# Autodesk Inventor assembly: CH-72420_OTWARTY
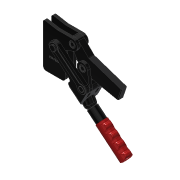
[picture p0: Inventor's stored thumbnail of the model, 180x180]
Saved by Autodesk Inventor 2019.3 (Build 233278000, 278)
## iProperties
Company: Î¢ÈíÖÐ¹ú
Created: 2013-06
Part Number: CH-72420_OTWARTY
Material: Ogólny
Description: STEP AP203
Document SubType Name: Assembly
Designer: CADENGINEERING4
Stock Number: DOCISK CIĘŻKI
Sending System: SolidWorks 2011
Preprocessor: SwSTEP 2.0
Title: CH-72420.STEP
Author: Î¢ÈíÓÃ»§
Revision Number: ÈÎºÎ
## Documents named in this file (12)
- D:\Vault_2016\Projekty\NASZ KATALOG\CLAMPTEK\STRONA\Heavy duty weldables\CH-72420\CH-72420_OTWARTY.iam
- D:\Vault_2016\Projekty\NASZ KATALOG\CLAMPTEK\STRONA\Heavy duty weldables\CH-72420\72425-08.ipt
- D:\Vault_2016\Projekty\NASZ KATALOG\CLAMPTEK\STRONA\Heavy duty weldables\CH-72420\72425-03.ipt
- D:\Vault_2016\Projekty\NASZ KATALOG\CLAMPTEK\STRONA\Heavy duty weldables\CH-72420\72425-06.ipt
- D:\Vault_2016\Projekty\NASZ KATALOG\CLAMPTEK\STRONA\Heavy duty weldables\CH-72420\CH-72420-02.ipt
- D:\Vault_2016\Projekty\NASZ KATALOG\CLAMPTEK\STRONA\Heavy duty weldables\CH-72420\72425-07.ipt
- D:\Vault_2016\Projekty\NASZ KATALOG\CLAMPTEK\STRONA\Heavy duty weldables\CH-72420\72425-10.ipt
- D:\Vault_2016\Projekty\NASZ KATALOG\CLAMPTEK\STRONA\Heavy duty weldables\CH-72420\M12.ipt
- D:\Vault_2016\Projekty\NASZ KATALOG\CLAMPTEK\STRONA\Heavy duty weldables\CH-72420\72415-04.ipt
- D:\Vault_2016\Projekty\NASZ KATALOG\CLAMPTEK\STRONA\Heavy duty weldables\CH-72420\72425-11.ipt
- D:\Vault_2016\Projekty\NASZ KATALOG\CLAMPTEK\STRONA\Heavy duty weldables\CH-72420\CH-72420-01.ipt
- D:\Vault_2016\Projekty\NASZ KATALOG\CLAMPTEK\STRONA\Heavy duty weldables\CH-72420\72425-09.ipt
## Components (18 placed, 11 different names)
1. CH-72420-01_17
2. 72425-08:3 — Zestawiające:7, Zestawiające:8, Zestawiające:9, Zestawiające:10, Zestawiające:11, Równoległe:7
3. 72425-03:3 — Zestawiające:13, Zestawiające:16, Równoległe:2, Równoległe:5, Równoległe:6, Zestawiające:20
4. 72425-08:4 — Zestawiające:16, Zestawiające:17, Zestawiające:18, Równoległe:6, Zestawiające:22
5. 72425-06:7 — Zestawiające:14, Równoległe:3
6. 72425-03:4 — Zestawiające:15, Zestawiające:19, Równoległe:3, Równoległe:4, Zestawiające:21, Zestawiające:23
7. 72425-06:8 — Zestawiające:9, Zestawiające:11, Zestawiające:25, Równoległe:7
8. CH-72420-02:2 — Zestawiające:8, Zestawiające:20, Zestawiające:21, Zestawiające:22, Zestawiające:24, Zestawiające:25, Równoległe:8
9. 72425-07:2 — Zestawiające:6, Równoległe:1, Zestawiające:12, Zestawiające:13, Zestawiające:14, Zestawiające:15
10. 72425-10:2 — Zestawiające:1, Zestawiające:2, Zestawiające:3, Zestawiające:4
11. 72425-06:9 — Zestawiające:17, Równoległe:5
12. M12:2 — Zestawiające:4, Zestawiające:5
13. 72425-06:10 — Zestawiające:7, Zestawiające:10, Zestawiające:24
14. 72425-06:11 — Zestawiające:18, Zestawiające:19, Równoległe:4
15. 72415-04:2 — Zestawiające:2, Zestawiające:3, Zestawiające:5, Zestawiające:6, Równoległe:1, Zestawiające:23, Zestawiające:26, Zestawiające:27
16. 72425-11:2 — Zestawiające:26, Zestawiające:27
17. 72425-06:12 — Zestawiające:12, Równoległe:2
18. 72425-09:2 — Zestawiające:1, Równoległe:8
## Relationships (35: Mate 27, Flush 8)
- Zestawiające:1 [Mate]: 72425-10:2 ↔ 72425-09:2
- Zestawiające:2 [Mate]: 72425-10:2 ↔ 72415-04:2
- Zestawiające:3 [Mate]: 72425-10:2 ↔ 72415-04:2
- Zestawiające:4 [Mate]: 72425-10:2 ↔ M12:2
- Zestawiające:5 [Mate]: M12:2 ↔ 72415-04:2
- Zestawiające:6 [Mate]: 72425-07:2 ↔ 72415-04:2
- Równoległe:1 [Flush]: 72425-07:2 ↔ 72415-04:2
- Zestawiające:7 [Mate]: 72425-08:3 ↔ 72425-06:10
- Zestawiające:8 [Mate]: 72425-08:3 ↔ CH-72420-02:2
- Zestawiające:9 [Mate]: 72425-08:3 ↔ 72425-06:8
- Zestawiające:10 [Mate]: 72425-08:3 ↔ 72425-06:10
- Zestawiające:11 [Mate]: 72425-08:3 ↔ 72425-06:8
- Zestawiające:12 [Mate]: 72425-07:2 ↔ 72425-06:12
- Zestawiające:13 [Mate]: 72425-03:3 ↔ 72425-07:2
- Zestawiające:14 [Mate]: 72425-06:7 ↔ 72425-07:2
- Zestawiające:15 [Mate]: 72425-03:4 ↔ 72425-07:2
- Zestawiające:16 [Mate]: 72425-03:3 ↔ 72425-08:4
- Zestawiające:17 [Mate]: 72425-08:4 ↔ 72425-06:9
- Zestawiające:18 [Mate]: 72425-08:4 ↔ 72425-06:11
- Zestawiające:19 [Mate]: 72425-03:4 ↔ 72425-06:11
- Równoległe:2 [Flush]: 72425-03:3 ↔ 72425-06:12
- Równoległe:3 [Flush]: 72425-06:7 ↔ 72425-03:4
- Równoległe:4 [Flush]: 72425-03:4 ↔ 72425-06:11
- Równoległe:5 [Flush]: 72425-03:3 ↔ 72425-06:9
- Równoległe:6 [Flush]: 72425-03:3 ↔ 72425-08:4
- Zestawiające:20 [Mate]: 72425-03:3 ↔ CH-72420-02:2
- Zestawiające:21 [Mate]: 72425-03:4 ↔ CH-72420-02:2
- Zestawiające:22 [Mate]: 72425-08:4 ↔ CH-72420-02:2
- Zestawiające:23 [Mate]: 72425-03:4 ↔ 72415-04:2
- Zestawiające:24 [Mate]: CH-72420-02:2 ↔ 72425-06:10
- Zestawiające:25 [Mate]: 72425-06:8 ↔ CH-72420-02:2
- Równoległe:7 [Flush]: 72425-08:3 ↔ 72425-06:8
- Zestawiające:26 [Mate]: 72415-04:2 ↔ 72425-11:2
- Zestawiające:27 [Mate]: 72415-04:2 ↔ 72425-11:2
- Równoległe:8 [Flush]: CH-72420-02:2 ↔ 72425-09:2
